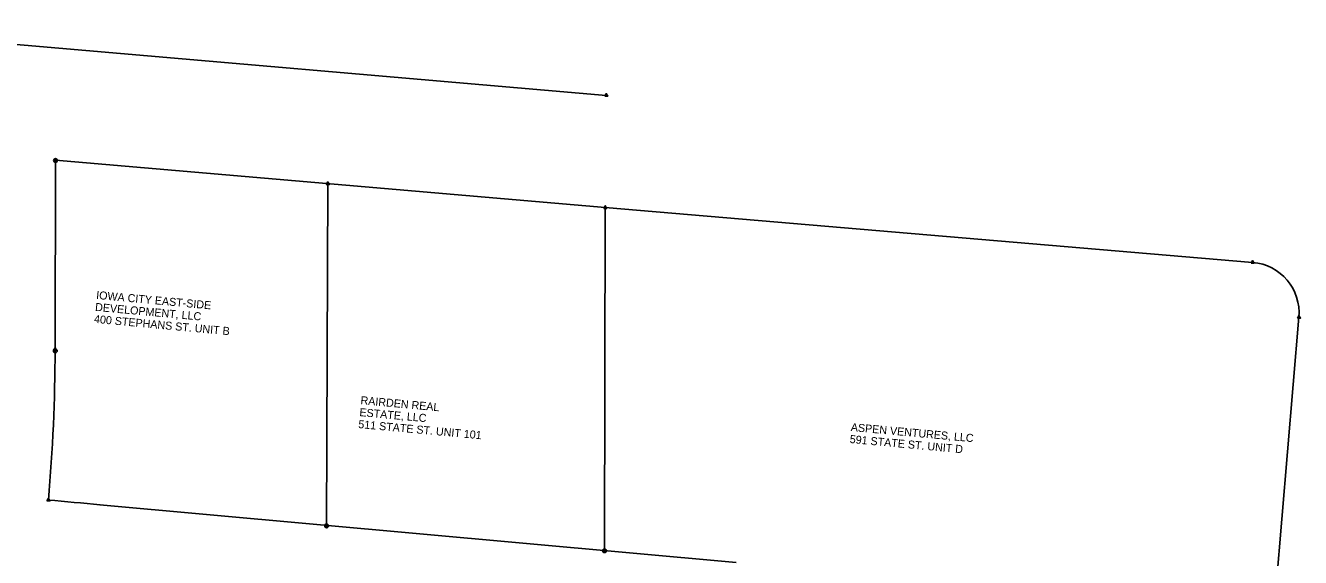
# Model space of a CAD drawing. Extents: x 20500076 to 20505422, y 7951999 to 7957351.
# Drawn here: x 20501783 to 20502535, y 7953933 to 7954247 of the extents above; entities that cross this region are included whole.
import ezdxf

# ---------------------------------------------------------------- set-up
doc = ezdxf.new("R2010")
doc.units = 0
for name, color, linetype in [('DisROW Existing', 7, 'Continuous'), ('DisROW Property Lines', 7, 'Continuous'), ('rowdsnSymbolsProposed', 7, 'Continuous'), ('SurControl', 7, 'Continuous'), ('SurSectionCorner', 7, 'Continuous'), ('Text', 7, 'Continuous')]:
    doc.layers.add(name, color=color, linetype=linetype)

msp = doc.modelspace()

# ---------------------------------------------------------------- linework, layer by layer
at = {"layer": 'DisROW Existing'}
for p, q in [((20502125.45, 7954206.14), (20501646.66, 7954247.4)), ((20501800.35, 7954167.91), (20501800.13, 7954055.99)), ((20502518.51, 7953887.39), (20502534.3, 7954075.17)), ((20501826.62, 7953964.54), (20502202.09, 7953930.47))]:
    msp.add_line(p, q, dxfattribs=at)
msp.add_lwpolyline([(20502506.94, 7954107.58), (20502124.85, 7954139.91), (20501800.35, 7954167.91)], dxfattribs=at)
for centre, radius, start, end in [((20502504.41, 7954077.69), 30, 355.18598, 85.16868), ((20500767.14, 7954057.98), 1033, 354.96366, 359.8895), ((20498089.14, 7912778.84), 41354.94, 84.814772, 84.857165)]:
    msp.add_arc(centre, radius, start, end, dxfattribs=at)
at = {"layer": 'DisROW Property Lines'}
for p, q in [((20501960.25, 7953952.42), (20501961.07, 7954154.06)), ((20502124.34, 7953937.52), (20502124.85, 7954139.91))]:
    msp.add_line(p, q, dxfattribs=at)
at = {"layer": 'rowdsnSymbolsProposed'}
for points in [[(20502125.45, 7954206.14), (20502125.45, 7954206.14)], [(20501800.35, 7954167.91), (20501800.35, 7954167.91)], [(20501961.07, 7954154.04), (20501961.08, 7954154.04)], [(20502124.85, 7954139.91), (20502124.85, 7954139.92)], [(20502506.94, 7954107.58), (20502506.94, 7954107.58)], [(20502534.3, 7954075.17), (20502534.31, 7954075.17)], [(20501800.13, 7954055.99), (20501800.14, 7954055.99)], [(20501796.15, 7953967.3), (20501796.15, 7953967.3)], [(20501960.25, 7953952.42), (20501960.25, 7953952.42)], [(20502124.34, 7953937.52), (20502124.35, 7953937.53)]]:
    msp.add_lwpolyline(points, dxfattribs=at)
at = {"layer": 'SurControl'}
for centre in [(20501800.39, 7954167.66), (20501800.24, 7954055.35), (20501960.39, 7953952.01), (20502124.4, 7953937.39)]:
    msp.add_circle(centre, 1.12, dxfattribs=at)
at = {"layer": 'SurSectionCorner'}
for points in [[(20502124.53, 7954205.61), (20502126.36, 7954205.61), (20502125.45, 7954207.19)], [(20501799.44, 7954167.38), (20501801.26, 7954167.38), (20501800.35, 7954168.96)], [(20501960.16, 7954153.51), (20501961.99, 7954153.51), (20501961.07, 7954155.1)], [(20502123.94, 7954139.38), (20502125.77, 7954139.38), (20502124.85, 7954140.97)], [(20502506.02, 7954107.05), (20502507.85, 7954107.05), (20502506.94, 7954108.63)], [(20502533.39, 7954074.64), (20502535.22, 7954074.64), (20502534.3, 7954076.23)], [(20501799.22, 7954055.46), (20501801.05, 7954055.46), (20501800.13, 7954057.04)], [(20501795.23, 7953966.77), (20501797.06, 7953966.77), (20501796.15, 7953968.35)], [(20501959.33, 7953951.89), (20501961.16, 7953951.89), (20501960.25, 7953953.47)], [(20502123.43, 7953937), (20502125.26, 7953937), (20502124.34, 7953938.58)]]:
    msp.add_lwpolyline(points, close=True, dxfattribs=at)

# ---------------------------------------------------------------- texts
at = {"layer": 'Text'}
for s, p in [('IOWA CITY EAST-SIDE', (20501824.22, 7954086.03)), ('DEVELOPMENT, LLC', (20501823.58, 7954078.97)), ('400 STEPHANS ST. UNIT B', (20501822.93, 7954071.91)), ('RAIRDEN REAL ', (20501980.24, 7954023.93)), ('ESTATE, LLC', (20501979.59, 7954016.87)), ('511 STATE ST. UNIT 101', (20501978.94, 7954009.81)), ('ASPEN VENTURES, LLC', (20502269.65, 7954008.06)), ('591 STATE ST. UNIT D', (20502269, 7954001))]:
    msp.add_text(s, height=4.7244, rotation=354.76449, dxfattribs=at).set_placement(p)

doc.saveas('drawing.dxf')
